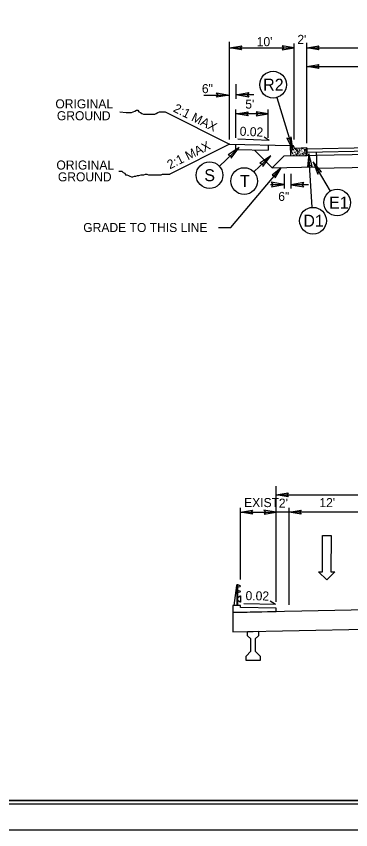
# Model space of a CAD drawing. Extents: x 1640342 to 1730599, y 538663 to 843747.
# Drawn here: x 1729954.3 to 1730006.2, y 538911.9 to 539037.8 of the extents above; entities that cross this region are included whole.
import ezdxf

# ---------------------------------------------------------------- set-up
doc = ezdxf.new("R2010")
doc.units = 0
for name, color, linetype in [('Default', 7, 'Continuous'), ('Prop Terminator CELL', 7, 'Continuous'), ('Sheet Clip Boundary CELL', 7, 'Continuous'), ('Sheet Layout Plan Border', 7, 'Continuous'), ('Sheet Plan CELL', 7, 'Continuous'), ('Sheet Plan Layout CELL', 7, 'Continuous'), ('Sheet Plot Border Inside CELL', 7, 'Continuous'), ('Sheet Plot Border Outside CELL', 7, 'Continuous'), ('Typical Curb CELL', 7, 'Continuous'), ('Typical Hinge Slope Arterial CELL', 7, 'Continuous'), ('Typical Hinge Slope Interstate CELL', 7, 'Continuous'), ('Typical ID Circle CELL', 7, 'Continuous'), ('Typical Pavement Slope CELL', 7, 'Continuous'), ('Typical Pavement Slope Information CELL', 7, 'Continuous'), ('Typical Shoulder Slope CELL', 7, 'Continuous'), ('Typical Terminator CELL', 7, 'Continuous'), ('Typical Text General CELL', 7, 'Continuous'), ('Typical Text ID Circle CELL', 7, 'Continuous')]:
    doc.layers.add(name, color=color, linetype=linetype)

msp = doc.modelspace()

# ---------------------------------------------------------------- linework, layer by layer
at = {"layer": 'Default'}
for p, q in [((1729987.36, 539018.78), (1729987.36, 539033.87)), ((1729987.36, 539032.94), (1729997.4, 539032.94)), ((1729997.36, 539018.78), (1729997.36, 539033.64)), ((1729999.33, 539018.18), (1729999.33, 539033.71)), ((1729999.33, 539032.94), (1730007.45, 539032.94)), ((1729999.33, 539030.06), (1730012.45, 539030.06)), ((1729988.36, 539027.31), (1729988.36, 539025.05)), ((1729983.39, 539025.65), (1729987.36, 539025.65)), ((1729991.11, 539025.67), (1729988.36, 539025.67)), ((1729988.36, 539019.03), (1729988.36, 539023.43)), ((1729993.36, 539022.74), (1729988.36, 539022.74)), ((1729993.36, 539019.03), (1729993.36, 539023.43)), ((1729995.85, 539013.44), (1729995.85, 539011.18)), ((1729996.85, 539013.44), (1729996.85, 539011.18)), ((1729993.69, 539011.8), (1729995.85, 539011.8)), ((1729999.58, 539011.77), (1729996.85, 539011.77)), ((1729994.59, 538947.19), (1729994.59, 538965.09)), ((1729994.59, 538963.76), (1730063.59, 538963.76)), ((1729989.07, 538950.63), (1729989.07, 538961.76)), ((1729989.07, 538961.06), (1729994.59, 538961.06)), ((1729996.59, 538961.06), (1729994.59, 538961.06)), ((1729996.59, 538946.73), (1729996.59, 538961.76)), ((1730008.59, 538961.06), (1729996.59, 538961.06)), ((1730001.76, 538951.86), (1730001.79, 538957.45)), ((1730001.79, 538957.45), (1730003.11, 538957.45)), ((1730003.11, 538957.45), (1730003.08, 538951.85)), ((1730002.43, 538950.6), (1730001.16, 538951.86)), ((1730001.16, 538951.86), (1730001.76, 538951.86)), ((1730003.68, 538951.85), (1730002.43, 538950.6)), ((1730003.08, 538951.85), (1730003.68, 538951.85))]:
    msp.add_line(p, q, dxfattribs=at)
for points in [[(1729989.24, 539032.62), (1729987.36, 539032.94), (1729989.25, 539033.28), (1729989.01, 539032.94)], [(1729995.52, 539032.62), (1729997.4, 539032.94), (1729995.51, 539033.28), (1729995.75, 539032.94)], [(1730001.21, 539032.62), (1729999.33, 539032.94), (1730001.22, 539033.28), (1730000.98, 539032.94)], [(1730001.21, 539029.74), (1729999.33, 539030.06), (1730001.22, 539030.39), (1730000.98, 539030.06)], [(1729990.24, 539022.42), (1729988.36, 539022.74), (1729990.25, 539023.07), (1729990.01, 539022.74)], [(1729991.49, 539022.42), (1729993.36, 539022.74), (1729991.48, 539023.07), (1729991.72, 539022.74)], [(1729996.46, 538963.44), (1729994.59, 538963.76), (1729996.47, 538964.09), (1729996.23, 538963.76)], [(1729990.94, 538960.74), (1729989.07, 538961.06), (1729990.95, 538961.4), (1729990.71, 538961.06)], [(1729992.71, 538960.74), (1729994.59, 538961.06), (1729992.7, 538961.4), (1729992.94, 538961.06)], [(1729998.46, 538960.74), (1729996.59, 538961.06), (1729998.47, 538961.4), (1729998.23, 538961.06)]]:
    msp.add_lwpolyline(points, close=True, dxfattribs=at)
at = {"layer": 'Prop Terminator CELL'}
msp.add_lwpolyline([(1729994.45, 539012.82), (1729995.38, 539014.4), (1729993.96, 539013.22), (1729994.36, 539013.19)], close=True, dxfattribs=at)
at = {"layer": 'Sheet Clip Boundary CELL'}
msp.add_lwpolyline([(1729883.99, 538916.42), (1730163.99, 538916.42), (1730163.99, 539084.12), (1730126.14, 539084.12), (1730126.14, 539126.42), (1729883.99, 539126.42)], close=True, dxfattribs=at)
at = {"layer": 'Sheet Layout Plan Border'}
msp.add_lwpolyline([(1729883.99, 538916.42), (1730163.99, 538916.42), (1730163.99, 539084.12), (1730126.14, 539084.12), (1730126.14, 539126.42), (1729883.99, 539126.42)], close=True, dxfattribs=at)
at = {"layer": 'Sheet Plan CELL'}
for points in [[(1730174, 539126.42), (1729873.99, 539126.42), (1729873.99, 538916.42), (1730173.99, 538916.42)], [(1729873.99, 538916.42), (1729873.99, 539126.41), (1730133.98, 539126.42), (1730133.99, 539096.41), (1730173.99, 539096.41), (1730173.99, 538916.42)]]:
    msp.add_lwpolyline(points, close=True, dxfattribs=at)
at = {"layer": 'Sheet Plan Layout CELL'}
msp.add_lwpolyline([(1729873.99, 539126.41), (1729873.99, 538916.42), (1730173.99, 538916.42), (1730173.99, 539084.12), (1730126.14, 539084.12), (1730126.14, 539126.42)], close=True, dxfattribs=at)
at = {"layer": 'Sheet Plot Border Inside CELL'}
msp.add_lwpolyline([(1729843.29, 538915.92), (1730176.49, 538915.92), (1730176.49, 539126.92), (1729843.29, 539126.92)], close=True, dxfattribs=at)
at = {"layer": 'Sheet Plot Border Outside CELL'}
msp.add_lwpolyline([(1729840.69, 538911.92), (1730177.39, 538911.92), (1730177.39, 539130.92), (1729840.69, 539130.92)], close=True, dxfattribs=at)
at = {"layer": 'Typical Curb CELL'}
for p, q in [((1729996.83, 539017.85), (1729997.09, 539017.86)), ((1729996.85, 539016.26), (1729996.83, 539017.85)), ((1729996.87, 539017.48), (1729997.03, 539017.52)), ((1729997.01, 539017.43), (1729996.87, 539017.48)), ((1729997, 539017.16), (1729996.9, 539017.08)), ((1729996.9, 539017.08), (1729997.07, 539017.05)), ((1729997.07, 539017.05), (1729997, 539017.16)), ((1729997.03, 539017.52), (1729997.01, 539017.43)), ((1729997.14, 539016.71), (1729997.03, 539016.63)), ((1729997.03, 539016.63), (1729997.2, 539016.6)), ((1729997.2, 539016.6), (1729997.14, 539016.71)), ((1729997.33, 539017.61), (1729997.33, 539017.62)), ((1729999.33, 539017.48), (1729997.59, 539017.38)), ((1729997.74, 539017.23), (1729997.71, 539017.11)), ((1729997.71, 539017.11), (1729997.83, 539017.11)), ((1729997.83, 539017.11), (1729997.74, 539017.23)), ((1729997.94, 539016.77), (1729997.84, 539016.69)), ((1729997.84, 539016.69), (1729998.01, 539016.65)), ((1729998.01, 539016.65), (1729997.94, 539016.77)), ((1729998.25, 539017.18), (1729998.15, 539017.1)), ((1729998.15, 539017.1), (1729998.31, 539017.07)), ((1729998.31, 539017.07), (1729998.25, 539017.18)), ((1729998.75, 539016.6), (1729998.64, 539016.52)), ((1729998.64, 539016.52), (1729998.81, 539016.49)), ((1729998.81, 539016.49), (1729998.75, 539016.6)), ((1729998.99, 539017.25), (1729998.96, 539017.13)), ((1729998.96, 539017.13), (1729999.08, 539017.13)), ((1729999.08, 539017.13), (1729998.99, 539017.25)), ((1729999.35, 539016.31), (1729999.33, 539017.48))]:
    msp.add_line(p, q, dxfattribs=at)
for centre in [(1729996.84, 539017.74), (1729997.06, 539017.78), (1729996.9, 539017.56), (1729996.9, 539016.6), (1729996.96, 539016.74), (1729996.97, 539016.43), (1729996.99, 539016.9), (1729997, 539017.29), (1729997.12, 539017.34), (1729997.12, 539016.45), (1729997.16, 539016.95), (1729997.29, 539016.5), (1729997.3, 539017.18), (1729997.34, 539016.89), (1729997.34, 539016.37), (1729997.38, 539017.38), (1729997.39, 539017), (1729997.39, 539017.33), (1729997.42, 539017.16), (1729997.43, 539016.73), (1729997.47, 539016.44), (1729997.51, 539016.92), (1729997.53, 539016.55), (1729997.56, 539016.71), (1729997.57, 539017.24), (1729997.6, 539017.35), (1729997.64, 539016.47), (1729997.71, 539016.94), (1729997.71, 539016.66), (1729997.76, 539016.8), (1729997.77, 539016.49), (1729997.79, 539017.31), (1729997.82, 539016.37), (1729997.87, 539016.88), (1729997.89, 539017.36), (1729997.92, 539017.11), (1729997.93, 539016.51), (1729998, 539017.27), (1729997.99, 539016.4), (1729998.02, 539017.07), (1729998.05, 539017.31), (1729998.07, 539017.21), (1729998.08, 539016.9), (1729998.1, 539016.55), (1729998.21, 539016.37), (1729998.24, 539016.92), (1729998.24, 539016.79), (1729998.25, 539017.31), (1729998.28, 539016.49), (1729998.33, 539016.61), (1729998.36, 539016.76), (1729998.37, 539017.36), (1729998.38, 539016.4), (1729998.41, 539016.96), (1729998.45, 539016.52), (1729998.51, 539016.49), (1729998.55, 539017.2), (1729998.57, 539016.63), (1729998.59, 539016.9), (1729998.62, 539017.4), (1729998.64, 539017.35), (1729998.64, 539017.02), (1729998.67, 539017.17), (1729998.72, 539016.7), (1729998.76, 539016.94), (1729998.82, 539017.26), (1729998.85, 539017.36), (1729998.89, 539016.73), (1729998.9, 539016.38), (1729998.96, 539016.96), (1729998.99, 539017.43), (1729999.04, 539017.33), (1729999.04, 539016.62), (1729999.06, 539016.76), (1729999.12, 539016.9), (1729999.14, 539017.41), (1729999.14, 539016.44), (1729999.17, 539017.13), (1729999.17, 539016.59), (1729999.23, 539016.79), (1729999.25, 539017.29), (1729999.27, 539017.09), (1729999.3, 539017.33), (1729999.32, 539017.23), (1729999.33, 539016.92), (1729997.17, 539016.34), (1729998.58, 539016.32), (1729998.73, 539016.34), (1729999.08, 539016.32), (1729999.25, 539016.36)]:
    msp.add_circle(centre, 0.00801, dxfattribs=at)
for centre, start, end in [((1729997.09, 539017.62), 0.8814, 90.8814), ((1729997.57, 539017.62), 180.8814, 273.2659)]:
    msp.add_arc(centre, 0.239, start, end, dxfattribs=at)
at = {"layer": 'Typical Hinge Slope Arterial CELL'}
for p, q in [((1729977.37, 539023.04), (1729987.36, 539018.04)), ((1729987.36, 539018.04), (1729978.14, 539013.42))]:
    msp.add_line(p, q, dxfattribs=at)
msp.add_lwpolyline([(1729970.35, 539023.04), (1729971.34, 539022.92), (1729971.58, 539022.92), (1729971.95, 539022.92), (1729972.2, 539022.92), (1729972.44, 539023.04), (1729972.69, 539023.16), (1729972.94, 539023.29), (1729973.18, 539023.29), (1729973.31, 539023.04), (1729973.55, 539022.92), (1729973.8, 539022.79), (1729974.05, 539022.67), (1729974.29, 539022.67), (1729974.54, 539022.67), (1729974.78, 539022.67), (1729975.03, 539022.67), (1729975.28, 539022.67), (1729975.52, 539022.67), (1729975.77, 539022.67), (1729976.01, 539022.79), (1729976.26, 539022.92), (1729976.51, 539023.04), (1729976.88, 539023.04), (1729977.12, 539023.04), (1729977.37, 539023.04)], dxfattribs=at)
at = {"layer": 'Typical Hinge Slope Interstate CELL'}
msp.add_lwpolyline([(1729970.2, 539013.88), (1729970.43, 539013.88), (1729970.66, 539013.88), (1729970.89, 539013.65), (1729971.12, 539013.54), (1729971.23, 539013.3), (1729971.46, 539013.3), (1729971.69, 539013.19), (1729971.92, 539013.07), (1729972.15, 539012.96), (1729972.39, 539012.96), (1729972.62, 539013.07), (1729972.85, 539013.07), (1729973.08, 539013.19), (1729973.31, 539013.19), (1729973.65, 539013.3), (1729973.88, 539013.3), (1729974.11, 539013.3), (1729974.34, 539013.42), (1729974.57, 539013.42), (1729974.8, 539013.3), (1729975.03, 539013.3), (1729975.27, 539013.3), (1729975.5, 539013.3), (1729975.73, 539013.3), (1729976.07, 539013.3), (1729976.42, 539013.3), (1729976.76, 539013.3), (1729976.99, 539013.42), (1729977.34, 539013.42), (1729977.68, 539013.42), (1729978.14, 539013.42)], dxfattribs=at)
at = {"layer": 'Typical ID Circle CELL'}
for p, q in [((1729994.72, 539025.26), (1729997.17, 539017.14)), ((1729985.79, 539014.65), (1729988.85, 539017.51)), ((1730000.19, 539008.25), (1729999.68, 539016.56)), ((1729991.14, 539013.74), (1729993.78, 539016.21)), ((1730002.99, 539010.79), (1730000.32, 539015.33))]:
    msp.add_line(p, q, dxfattribs=at)
for centre in [(1729994.12, 539027.25), (1729984.27, 539013.24), (1729989.63, 539012.33), (1730004.04, 539009), (1730000.3, 539006.19)]:
    msp.add_circle(centre, 2.07, dxfattribs=at)
at = {"layer": 'Typical Pavement Slope CELL'}
for p, q in [((1729999.35, 539017.31), (1730029.51, 539017.91)), ((1729991.22, 539017.13), (1729993.98, 539014.37)), ((1729999.35, 539017.48), (1729999.35, 539016.31)), ((1729999.35, 539016.81), (1730029.51, 539017.41)), ((1730000.83, 539016.34), (1730029.52, 539016.91)), ((1730000.83, 539016.37), (1730000.83, 539016.87)), ((1729995.85, 539016.24), (1729993.98, 539014.37)), ((1729995.85, 539016.24), (1729999.35, 539016.31)), ((1729999.33, 539016.31), (1730000.83, 539016.34)), ((1729993.98, 539014.37), (1730000.78, 539014.51)), ((1730000.83, 539014.34), (1730029.51, 539014.91))]:
    msp.add_line(p, q, dxfattribs=at)
for points in [[(1730000.83, 539016.37), (1730000.83, 539014.34)], [(1729988.52, 538949.8), (1729988.44, 538949.72), (1729988.05, 538946.64)], [(1729988.67, 538949.8), (1729988.52, 538949.8)], [(1729988.52, 538949.8), (1729988.52, 538946.64)], [(1729988.67, 538946.64), (1729988.67, 538949.8)], [(1729988.67, 538949.8), (1729988.75, 538949.8), (1729988.98, 538949.74), (1729989.07, 538949.63)], [(1729989.07, 538949.63), (1729988.98, 538949.53), (1729988.75, 538949.47), (1729988.67, 538949.47)], [(1729988.67, 538948.97), (1729988.75, 538948.97), (1729988.98, 538948.91), (1729989.07, 538948.8)], [(1729989.07, 538948.8), (1729988.98, 538948.7), (1729988.75, 538948.63), (1729988.67, 538948.63)], [(1730070.11, 538947.2), (1729998.59, 538945.77), (1729987.88, 538945.56)], [(1729988.67, 538947.89), (1729989, 538948.13), (1729989.09, 538948.14)], [(1729989.09, 538947.14), (1729989, 538947.16), (1729988.67, 538947.39)], [(1729989.09, 538948.14), (1729989.09, 538947.14)], [(1729987.88, 538945.56), (1729987.88, 538942.56)], [(1729987.88, 538942.56), (1730070.11, 538944.2)], [(1729990.17, 538942.6), (1729991.01, 538942.62), (1729991.84, 538942.64)], [(1729990.17, 538941.95), (1729990.17, 538942.6)], [(1729991.84, 538942.64), (1729991.84, 538941.95)], [(1729990.67, 538941.45), (1729990.17, 538941.95)], [(1729990.67, 538939.54), (1729990.67, 538941.45)], [(1729991.84, 538941.95), (1729991.34, 538941.45)], [(1729991.34, 538941.45), (1729991.34, 538939.54)], [(1729989.92, 538938.79), (1729990.67, 538939.54)], [(1729989.92, 538938.12), (1729989.92, 538938.79)], [(1729991.34, 538939.54), (1729992.09, 538938.79)], [(1729992.09, 538938.79), (1729992.09, 538938.12)], [(1729992.09, 538938.12), (1729991.01, 538938.12), (1729989.92, 538938.12)]]:
    msp.add_lwpolyline(points, dxfattribs=at)
at = {"layer": 'Typical Pavement Slope Information CELL'}
for p, q in [((1729993.53, 539018.59), (1729992.71, 539019.11)), ((1729993.53, 539018.59), (1729988.63, 539018.79)), ((1729994.47, 538946.79), (1729993.64, 538947.29)), ((1729994.47, 538946.79), (1729989.57, 538946.89))]:
    msp.add_line(p, q, dxfattribs=at)
at = {"layer": 'Typical Shoulder Slope CELL'}
for p, q in [((1729987.36, 539018.04), (1729996.83, 539017.85)), ((1729988.36, 539017.19), (1729988.36, 539018.02)), ((1729993.36, 539017.92), (1729993.36, 539017.09)), ((1729988.36, 539017.19), (1729993.36, 539017.09))]:
    msp.add_line(p, q, dxfattribs=at)
for points in [[(1729994.59, 538945.69), (1729994.59, 538946.19), (1729989.09, 538946.3), (1729989.09, 538946.64), (1729987.88, 538946.64), (1729987.88, 538945.56)], [(1729987.88, 538945.56), (1729994.59, 538945.69)]]:
    msp.add_lwpolyline(points, dxfattribs=at)
at = {"layer": 'Typical Terminator CELL'}
for p, q in [((1729987.55, 539005.14), (1729995.38, 539014.4)), ((1729985.64, 539005.14), (1729987.55, 539005.14))]:
    msp.add_line(p, q, dxfattribs=at)
for points in [[(1729985.35, 539025.99), (1729987.36, 539025.65), (1729985.34, 539025.29), (1729985.6, 539025.65)], [(1729990.37, 539025.33), (1729988.36, 539025.67), (1729990.38, 539026.03), (1729990.12, 539025.67)], [(1729996.26, 539018.96), (1729997.17, 539017.14), (1729996.93, 539019.17), (1729996.66, 539018.82)], [(1729987.62, 539015.89), (1729988.85, 539017.51), (1729987.13, 539016.39), (1729987.56, 539016.31)], [(1730000.15, 539014.58), (1729999.68, 539016.56), (1729999.45, 539014.52), (1729999.79, 539014.8)], [(1729992.55, 539014.59), (1729993.78, 539016.21), (1729992.06, 539015.09), (1729992.49, 539015.01)], [(1730001.64, 539013.77), (1730000.32, 539015.33), (1730001.04, 539013.41), (1730001.21, 539013.81)], [(1729993.85, 539011.45), (1729995.85, 539011.8), (1729993.84, 539012.15), (1729994.09, 539011.8)], [(1729998.86, 539012.12), (1729996.85, 539011.77), (1729998.87, 539011.42), (1729998.62, 539011.77)]]:
    msp.add_lwpolyline(points, close=True, dxfattribs=at)

# ---------------------------------------------------------------- texts
at = {"layer": 'Default'}
for s, p in [("10'", (1729991.58, 539033.21)), ('6"', (1729983.08, 539025.94)), ('ORIGINAL', (1729960.38, 539023.58)), ("5'", (1729989.81, 539023.54)), ('GROUND', (1729960.61, 539021.74)), ('ORIGINAL', (1729960.54, 539014.11)), ('GROUND', (1729960.77, 539012.28))]:
    msp.add_text(s, height=1.4, dxfattribs=at).set_placement(p)
for s, rotation, p in [('6"', 360, (1729994.92, 539009.25)), ('EXIST', 0, (1729989.62, 538961.86))]:
    msp.add_text(s, height=1.4, rotation=rotation, dxfattribs=at).set_placement(p)
at = {"layer": 'Typical Hinge Slope Interstate CELL'}
for rotation, p in [(333.4354, (1729978.54, 539023.14)), (26.5646, (1729978.13, 539014.13))]:
    msp.add_text('2:1 MAX', height=1.4, rotation=rotation, dxfattribs=at).set_placement(p)
at = {"layer": 'Typical Pavement Slope Information CELL'}
for s, p in [("2'", (1729997.88, 539033.56)), ("2'", (1729995.01, 538961.77)), ("12'", (1730001.29, 538961.85))]:
    msp.add_text(s, height=1.4, dxfattribs=at).set_placement(p)
for rotation, p in [(357.6997, (1729988.92, 539019.35)), (358.8541, (1729989.84, 538947.46))]:
    msp.add_text('0.02', height=1.4, rotation=rotation, dxfattribs=at).set_placement(p)
at = {"layer": 'Typical Text General CELL'}
msp.add_text('GRADE TO THIS LINE', height=1.4, dxfattribs=at).set_placement((1729964.7, 539004.44))
at = {"layer": 'Typical Text ID Circle CELL'}
for s, height, p in [('R2', 1.854, (1729992.58, 539026.32)), ('S', 1.85, (1729983.46, 539012.31)), ('T', 1.85, (1729988.99, 539011.4)), ('E1', 1.854, (1730002.8, 539008.08)), ('D1', 1.854, (1729998.81, 539005.26))]:
    msp.add_text(s, height=height, dxfattribs=at).set_placement(p)

doc.saveas('drawing.dxf')
